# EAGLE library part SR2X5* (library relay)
Safety Relay 2 pole 6 A SCHRACK Source: http://www.schrack.com/.. 5809.pdf
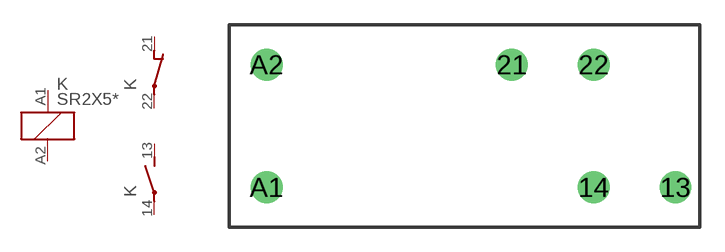
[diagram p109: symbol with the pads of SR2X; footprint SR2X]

Designator prefix K; gates 1=K 2=O 3=S

## SR2X5005 (OC_FARNELL: unknown; OC_NEWARK: unknown), SR2X5006 (OC_FARNELL: unknown; OC_NEWARK: unknown), SR2X5009 (OC_FARNELL: unknown; OC_NEWARK: unknown), SR2X5012 (OC_FARNELL: unknown; OC_NEWARK: unknown), SR2X5018 (OC_FARNELL: unknown; OC_NEWARK: unknown), SR2X5021 (OC_FARNELL: unknown; OC_NEWARK: unknown), SR2X5024 (OC_FARNELL: unknown; OC_NEWARK: unknown), SR2X5036 (OC_FARNELL: unknown; OC_NEWARK: unknown), SR2X5040 (OC_FARNELL: unknown; OC_NEWARK: unknown), SR2X5048 (OC_FARNELL: unknown; OC_NEWARK: unknown), SR2X5060 (OC_FARNELL: unknown; OC_NEWARK: unknown), SR2X5080 (OC_FARNELL: unknown; OC_NEWARK: unknown), SR2X5110 (OC_FARNELL: unknown; OC_NEWARK: unknown)  [SR2X]
13  3:S  pas
14  3:P  pas
21  2:O  pas
22  2:P  pas
A1  1:1  pas
A2  1:2  pas

## Footprint SR2X (pad centres in mm)
Safety Relay 2 pole 6 A SCHRACK Source: http://www.schrack.com/.. 5807.pdf
drill 1.3 round: 13 12.54,-3.75; 14 7.54,-3.75; 21 2.54,3.75; 22 7.54,3.75; A1 -12.46,-3.75; A2 -12.46,3.75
